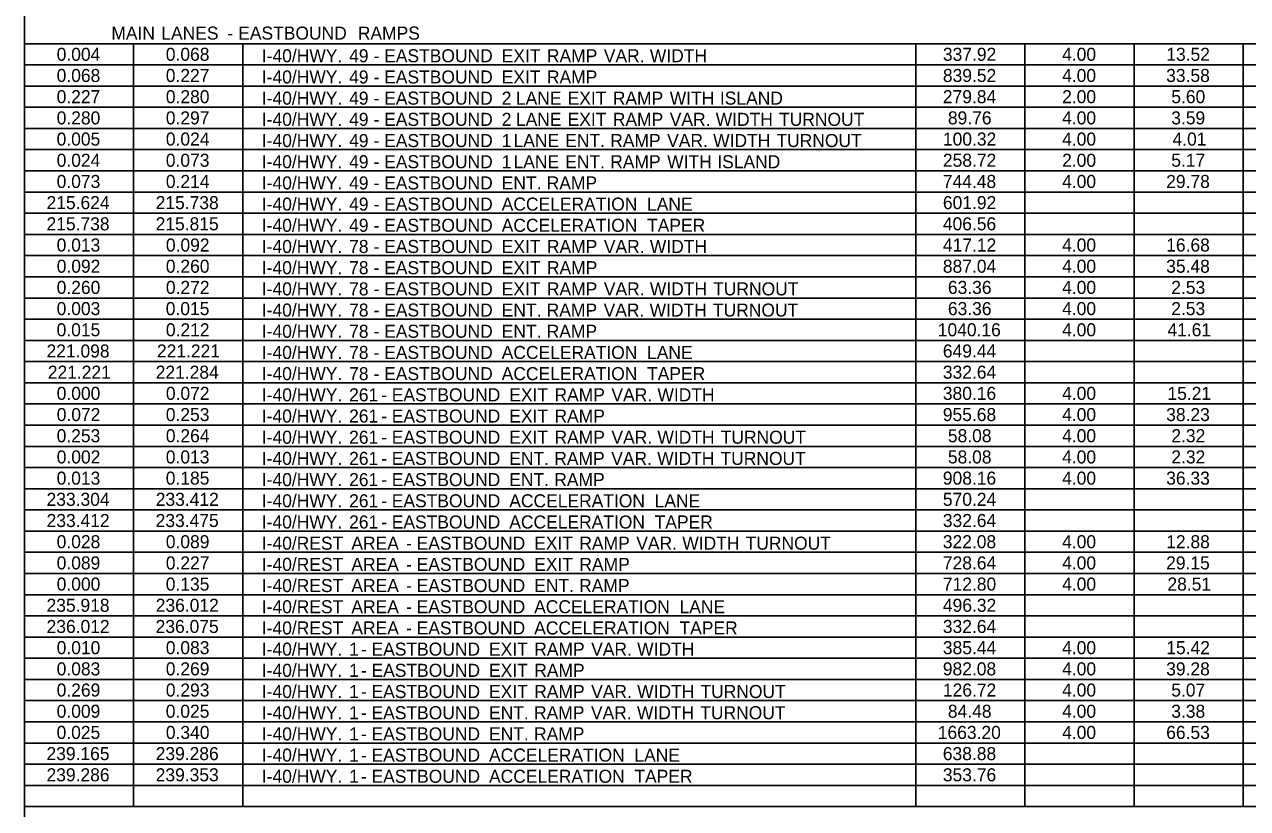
# Model space of a CAD drawing. Extents: x 2261867 to 2275370, y -3124789 to -3122260.
# Drawn here: x 2269380 to 2269943, y -3123269 to -3122908 of the extents above; entities that cross this region are included whole.
import ezdxf

# ---------------------------------------------------------------- set-up
doc = ezdxf.new("R2010")
doc.units = 0
doc.layers.add('Default', color=7, linetype='Continuous')

msp = doc.modelspace()

# ---------------------------------------------------------------- linework, layer by layer
at = {"layer": 'Default'}
for p, q in [((2269380.47, -3123434.1), (2269380.47, -3122273.85)), ((2269380.47, -3123434.1), (2269380.47, -3122273.85)), ((2269380.47, -3122917.35), (2270507.08, -3122917.35)), ((2269430.68, -3123268.35), (2269430.68, -3122917.35)), ((2269480.89, -3123268.35), (2269480.89, -3122917.35)), ((2269480.89, -3123268.35), (2269480.89, -3122917.35)), ((2269790.46, -3123268.35), (2269790.46, -3122917.35)), ((2269790.46, -3123268.35), (2269790.46, -3122917.35)), ((2269840.67, -3123268.35), (2269840.67, -3122917.35)), ((2269840.67, -3123268.35), (2269840.67, -3122917.35)), ((2269890.88, -3123268.35), (2269890.88, -3122917.35)), ((2269890.88, -3123268.35), (2269890.88, -3122917.35)), ((2269941.09, -3123268.35), (2269941.09, -3122917.35)), ((2269941.09, -3123268.35), (2269941.09, -3122917.35)), ((2269380.47, -3122927.1), (2270507.08, -3122927.1)), ((2269430.68, -3123268.35), (2269430.68, -3122927.1)), ((2269380.47, -3122936.85), (2270507.08, -3122936.85)), ((2269380.47, -3122946.6), (2270507.08, -3122946.6)), ((2269380.47, -3122956.35), (2270507.08, -3122956.35)), ((2269380.47, -3122966.1), (2270507.08, -3122966.1)), ((2269380.47, -3122975.85), (2270507.08, -3122975.85)), ((2269380.47, -3122985.6), (2270507.08, -3122985.6)), ((2269380.47, -3122995.35), (2270507.08, -3122995.35)), ((2269380.47, -3123005.1), (2270507.08, -3123005.1)), ((2269380.47, -3123014.85), (2270507.08, -3123014.85)), ((2269380.47, -3123024.6), (2270507.08, -3123024.6)), ((2269380.47, -3123034.35), (2270507.08, -3123034.35)), ((2269380.47, -3123044.1), (2270507.08, -3123044.1)), ((2269380.47, -3123053.85), (2270507.08, -3123053.85)), ((2269380.47, -3123063.6), (2270507.08, -3123063.6)), ((2269380.47, -3123073.35), (2270507.08, -3123073.35)), ((2269380.47, -3123083.1), (2270507.08, -3123083.1)), ((2269380.47, -3123092.85), (2270507.08, -3123092.85)), ((2269380.47, -3123102.6), (2270507.08, -3123102.6)), ((2269380.47, -3123112.35), (2270507.08, -3123112.35)), ((2269380.47, -3123122.1), (2270507.08, -3123122.1)), ((2269380.47, -3123131.85), (2270507.08, -3123131.85)), ((2269380.47, -3123141.6), (2270507.08, -3123141.6)), ((2269380.47, -3123151.35), (2270507.08, -3123151.35)), ((2269380.47, -3123161.1), (2270507.08, -3123161.1)), ((2269380.47, -3123170.85), (2270507.08, -3123170.85)), ((2269380.47, -3123180.6), (2270507.08, -3123180.6)), ((2269380.47, -3123190.35), (2270507.08, -3123190.35)), ((2269380.47, -3123200.1), (2270507.08, -3123200.1)), ((2269380.47, -3123209.85), (2270507.08, -3123209.85)), ((2269380.47, -3123219.6), (2270507.08, -3123219.6)), ((2269380.47, -3123229.35), (2270507.08, -3123229.35)), ((2269380.47, -3123239.1), (2270507.08, -3123239.1)), ((2269380.47, -3123248.85), (2270507.08, -3123248.85)), ((2269380.47, -3123258.6), (2270507.08, -3123258.6)), ((2269380.47, -3123268.35), (2270507.08, -3123268.35)), ((2269380.47, -3123268.35), (2270507.08, -3123268.35))]:
    msp.add_line(p, q, dxfattribs=at)

# ---------------------------------------------------------------- texts
for s, p in [('MAIN', (2269420.44, -3122915.47)), (' LANES', (2269441.19, -3122915.47)), (' EASTBOUND', (2269476.58, -3122915.47)), (' RAMPS', (2269531.6, -3122915.47)), (' -', (2269471.53, -3122915.47)), ('0.004', (2269395.29, -3122925.22)), ('0.068', (2269445.49, -3122925.22)), ('I-40/HWY.', (2269489.67, -3122925.9)), (' 49', (2269527.59, -3122925.9)), (' EASTBOUND', (2269543.72, -3122925.9)), (' EXIT', (2269597.78, -3122925.9)), (' RAMP', (2269618.58, -3122925.9)), (' VAR.', (2269644.76, -3122925.9)), (' WIDTH', (2269665.93, -3122925.9)), ('337.92', (2269802.97, -3122925.22)), ('4.00', (2269857.82, -3122925.22)), ('13.52', (2269905.73, -3122925.22)), (' -', (2269538.87, -3122925.9)), ('0.068', (2269395.28, -3122934.97)), ('0.227', (2269445.49, -3122934.97)), ('I-40/HWY.', (2269489.67, -3122935.65)), (' 49', (2269527.59, -3122935.65)), (' EASTBOUND', (2269543.72, -3122935.65)), (' EXIT', (2269597.78, -3122935.65)), (' RAMP', (2269618.58, -3122935.65)), ('839.52', (2269802.97, -3122934.97)), ('4.00', (2269857.82, -3122934.97)), ('33.58', (2269905.69, -3122934.97)), (' -', (2269538.87, -3122935.65)), ('0.227', (2269395.28, -3122944.72)), ('0.280', (2269445.51, -3122944.72)), ('I-40/HWY.', (2269489.67, -3122945.4)), (' 49', (2269527.59, -3122945.4)), (' -', (2269538.87, -3122945.4)), (' EASTBOUND', (2269543.72, -3122945.4)), (' 2', (2269597.78, -3122945.4)), (' LANE', (2269604.33, -3122945.4)), (' EXIT', (2269628.11, -3122945.4)), (' RAMP', (2269648.9, -3122945.4)), (' WITH', (2269675.09, -3122945.4)), (' ISLAND', (2269698.16, -3122945.4)), ('279.84', (2269802.95, -3122944.72)), ('2.00', (2269857.82, -3122944.72)), ('5.60', (2269908.04, -3122944.72)), ('0.280', (2269395.29, -3122954.47)), ('0.297', (2269445.49, -3122954.47)), ('I-40/HWY.', (2269489.67, -3122955.15)), (' 49', (2269527.59, -3122955.15)), (' EASTBOUND', (2269543.72, -3122955.15)), (' 2', (2269597.78, -3122955.15)), (' TURNOUT', (2269725.37, -3122955.15)), ('89.76', (2269805.27, -3122954.47)), ('4.00', (2269857.82, -3122954.47)), ('3.59', (2269908.02, -3122954.47)), (' -', (2269538.87, -3122955.15)), (' LANE', (2269604.33, -3122955.15)), (' EXIT', (2269628.11, -3122955.15)), (' RAMP', (2269648.9, -3122955.15)), (' VAR.', (2269675.09, -3122955.15)), (' WIDTH', (2269696.25, -3122955.15)), ('0.005', (2269395.26, -3122964.22)), ('0.024', (2269445.51, -3122964.22)), ('I-40/HWY.', (2269489.67, -3122964.9)), (' 49', (2269527.59, -3122964.9)), (' EASTBOUND', (2269543.72, -3122964.9)), (' 1', (2269597.78, -3122964.9)), (' LANE', (2269603.23, -3122964.9)), (' ENT.', (2269627.01, -3122964.9)), (' RAMP', (2269647.7, -3122964.9)), (' VAR.', (2269673.89, -3122964.9)), (' WIDTH', (2269695.05, -3122964.9)), (' TURNOUT', (2269724.18, -3122964.9)), ('100.32', (2269802.97, -3122964.22)), ('4.00', (2269857.82, -3122964.22)), ('4.01', (2269908.6, -3122964.22)), (' -', (2269538.87, -3122964.9)), ('0.024', (2269395.29, -3122973.97)), ('0.073', (2269445.49, -3122973.97)), ('I-40/HWY.', (2269489.67, -3122974.65)), (' 49', (2269527.59, -3122974.65)), (' EASTBOUND', (2269543.72, -3122974.65)), (' 1', (2269597.78, -3122974.65)), (' LANE', (2269603.23, -3122974.65)), (' ENT.', (2269627.01, -3122974.65)), (' RAMP', (2269647.7, -3122974.65)), (' WITH', (2269673.89, -3122974.65)), (' ISLAND', (2269696.96, -3122974.65)), ('258.72', (2269802.97, -3122973.97)), ('2.00', (2269857.82, -3122973.97)), ('5.17', (2269908.02, -3122973.97)), (' -', (2269538.87, -3122974.65)), ('0.073', (2269395.28, -3122983.72)), ('0.214', (2269445.51, -3122983.72)), ('I-40/HWY.', (2269489.67, -3122984.4)), (' 49', (2269527.59, -3122984.4)), (' -', (2269538.87, -3122984.4)), (' EASTBOUND', (2269543.72, -3122984.4)), (' ENT.', (2269597.78, -3122984.4)), (' RAMP', (2269618.48, -3122984.4)), ('744.48', (2269802.93, -3122983.72)), ('4.00', (2269857.82, -3122983.72)), ('29.78', (2269905.69, -3122983.72)), ('215.624', (2269390.63, -3122993.47)), ('215.738', (2269440.83, -3122993.47)), ('I-40/HWY.', (2269489.67, -3122994.15)), (' 49', (2269527.59, -3122994.15)), (' EASTBOUND', (2269543.72, -3122994.15)), (' ACCELERATION', (2269597.78, -3122994.15)), (' LANE', (2269664.65, -3122994.15)), ('601.92', (2269802.97, -3122993.47)), (' -', (2269538.87, -3122994.15)), ('215.738', (2269390.62, -3123003.22)), ('215.815', (2269440.81, -3123003.22)), ('I-40/HWY.', (2269489.67, -3123003.9)), (' 49', (2269527.59, -3123003.9)), (' EASTBOUND', (2269543.72, -3123003.9)), (' ACCELERATION', (2269597.78, -3123003.9)), (' TAPER', (2269664.65, -3123003.9)), ('406.56', (2269802.94, -3123003.22)), (' -', (2269538.87, -3123003.9)), ('0.013', (2269395.28, -3123012.97)), ('0.092', (2269445.53, -3123012.97)), ('I-40/HWY.', (2269489.67, -3123013.65)), (' 78', (2269527.59, -3123013.65)), (' EASTBOUND', (2269543.72, -3123013.65)), (' EXIT', (2269597.78, -3123013.65)), (' RAMP', (2269618.58, -3123013.65)), (' VAR.', (2269644.76, -3123013.65)), (' WIDTH', (2269665.93, -3123013.65)), ('417.12', (2269802.97, -3123012.97)), ('4.00', (2269857.82, -3123012.97)), ('16.68', (2269905.69, -3123012.97)), (' -', (2269538.87, -3123013.65)), ('0.092', (2269395.31, -3123022.72)), ('0.260', (2269445.51, -3123022.72)), ('I-40/HWY.', (2269489.67, -3123023.4)), (' 78', (2269527.59, -3123023.4)), (' -', (2269538.87, -3123023.4)), (' EASTBOUND', (2269543.72, -3123023.4)), (' EXIT', (2269597.78, -3123023.4)), (' RAMP', (2269618.58, -3123023.4)), ('887.04', (2269802.95, -3123022.72)), ('4.00', (2269857.82, -3123022.72)), ('35.48', (2269905.69, -3123022.72)), ('0.260', (2269395.29, -3123032.47)), ('0.272', (2269445.53, -3123032.47)), ('I-40/HWY.', (2269489.67, -3123033.15)), (' 78', (2269527.59, -3123033.15)), (' EASTBOUND', (2269543.72, -3123033.15)), (' EXIT', (2269597.78, -3123033.15)), (' RAMP', (2269618.58, -3123033.15)), (' VAR.', (2269644.76, -3123033.15)), (' WIDTH', (2269665.93, -3123033.15)), (' TURNOUT', (2269695.05, -3123033.15)), ('63.36', (2269805.27, -3123032.47)), ('4.00', (2269857.82, -3123032.47)), ('2.53', (2269908.02, -3123032.47)), (' -', (2269538.87, -3123033.15)), ('0.003', (2269395.28, -3123042.22)), ('0.015', (2269445.47, -3123042.22)), ('I-40/HWY.', (2269489.67, -3123042.9)), (' 78', (2269527.59, -3123042.9)), (' EASTBOUND', (2269543.72, -3123042.9)), (' ENT.', (2269597.78, -3123042.9)), (' RAMP', (2269618.48, -3123042.9)), (' VAR.', (2269644.66, -3123042.9)), (' WIDTH', (2269665.83, -3123042.9)), (' TURNOUT', (2269694.95, -3123042.9)), ('63.36', (2269805.27, -3123042.22)), ('4.00', (2269857.82, -3123042.22)), ('2.53', (2269908.02, -3123042.22)), (' -', (2269538.87, -3123042.9)), ('0.015', (2269395.26, -3123051.97)), ('0.212', (2269445.53, -3123051.97)), ('I-40/HWY.', (2269489.67, -3123052.65)), (' 78', (2269527.59, -3123052.65)), (' -', (2269538.87, -3123052.65)), (' EASTBOUND', (2269543.72, -3123052.65)), (' ENT.', (2269597.78, -3123052.65)), (' RAMP', (2269618.48, -3123052.65)), ('1040.16', (2269800.61, -3123051.97)), ('4.00', (2269857.82, -3123051.97)), ('41.61', (2269906.27, -3123051.97)), ('221.098', (2269390.62, -3123061.72)), ('221.221', (2269441.41, -3123061.72)), ('649.44', (2269802.95, -3123061.72)), ('I-40/HWY.', (2269489.67, -3123062.4)), (' 78', (2269527.59, -3123062.4)), (' -', (2269538.87, -3123062.4)), (' EASTBOUND', (2269543.72, -3123062.4)), (' ACCELERATION', (2269597.78, -3123062.4)), (' LANE', (2269664.65, -3123062.4)), ('221.221', (2269391.2, -3123071.47)), ('221.284', (2269440.85, -3123071.47)), ('I-40/HWY.', (2269489.67, -3123072.15)), (' 78', (2269527.59, -3123072.15)), (' EASTBOUND', (2269543.72, -3123072.15)), (' ACCELERATION', (2269597.78, -3123072.15)), (' TAPER', (2269664.65, -3123072.15)), ('332.64', (2269802.95, -3123071.47)), (' -', (2269538.87, -3123072.15)), ('0.000', (2269395.29, -3123081.22)), ('0.072', (2269445.53, -3123081.22)), ('I-40/HWY.', (2269489.67, -3123081.9)), (' 261', (2269527.59, -3123081.9)), (' EASTBOUND', (2269547.21, -3123081.9)), (' EXIT', (2269601.27, -3123081.9)), (' RAMP', (2269622.07, -3123081.9)), (' VAR.', (2269648.25, -3123081.9)), (' WIDTH', (2269669.42, -3123081.9)), ('380.16', (2269802.94, -3123081.22)), ('4.00', (2269857.82, -3123081.22)), ('15.21', (2269906.27, -3123081.22)), (' -', (2269542.36, -3123081.9)), ('0.072', (2269395.31, -3123090.97)), ('0.253', (2269445.49, -3123090.97)), ('I-40/HWY.', (2269489.67, -3123091.65)), (' 261', (2269527.59, -3123091.65)), (' -', (2269542.36, -3123091.65)), (' EASTBOUND', (2269547.21, -3123091.65)), (' EXIT', (2269601.27, -3123091.65)), (' RAMP', (2269622.07, -3123091.65)), ('955.68', (2269802.93, -3123090.97)), ('4.00', (2269857.82, -3123090.97)), ('38.23', (2269905.69, -3123090.97)), ('0.253', (2269395.28, -3123100.72)), ('0.264', (2269445.51, -3123100.72)), ('I-40/HWY.', (2269489.67, -3123101.4)), (' 261', (2269527.59, -3123101.4)), (' EASTBOUND', (2269547.21, -3123101.4)), (' TURNOUT', (2269698.54, -3123101.4)), ('58.08', (2269805.26, -3123100.72)), ('4.00', (2269857.82, -3123100.72)), ('2.32', (2269908.06, -3123100.72)), (' -', (2269542.36, -3123101.4)), (' EXIT', (2269601.27, -3123101.4)), (' RAMP', (2269622.07, -3123101.4)), (' VAR.', (2269648.25, -3123101.4)), (' WIDTH', (2269669.42, -3123101.4)), ('0.002', (2269395.31, -3123110.47)), ('0.013', (2269445.49, -3123110.47)), ('I-40/HWY.', (2269489.67, -3123111.15)), (' 261', (2269527.59, -3123111.15)), (' EASTBOUND', (2269547.21, -3123111.15)), (' ENT.', (2269601.27, -3123111.15)), (' RAMP', (2269621.97, -3123111.15)), (' VAR.', (2269648.15, -3123111.15)), (' WIDTH', (2269669.32, -3123111.15)), (' TURNOUT', (2269698.44, -3123111.15)), ('58.08', (2269805.26, -3123110.47)), ('4.00', (2269857.82, -3123110.47)), ('2.32', (2269908.06, -3123110.47)), (' -', (2269542.36, -3123111.15)), ('0.013', (2269395.28, -3123120.22)), ('0.185', (2269445.47, -3123120.22)), ('I-40/HWY.', (2269489.67, -3123120.9)), (' 261', (2269527.59, -3123120.9)), (' EASTBOUND', (2269547.21, -3123120.9)), (' ENT.', (2269601.27, -3123120.9)), (' RAMP', (2269621.97, -3123120.9)), ('908.16', (2269802.94, -3123120.22)), ('4.00', (2269857.82, -3123120.22)), ('36.33', (2269905.69, -3123120.22)), (' -', (2269542.36, -3123120.9)), ('233.304', (2269390.63, -3123129.97)), ('233.412', (2269440.87, -3123129.97)), ('I-40/HWY.', (2269489.67, -3123130.65)), (' 261', (2269527.59, -3123130.65)), (' -', (2269542.36, -3123130.65)), (' EASTBOUND', (2269547.21, -3123130.65)), (' ACCELERATION', (2269601.27, -3123130.65)), (' LANE', (2269668.14, -3123130.65)), ('570.24', (2269802.95, -3123129.97)), ('233.412', (2269390.65, -3123139.72)), ('233.475', (2269440.81, -3123139.72)), ('I-40/HWY.', (2269489.67, -3123140.4)), (' 261', (2269527.59, -3123140.4)), (' EASTBOUND', (2269547.21, -3123140.4)), (' ACCELERATION', (2269601.27, -3123140.4)), (' TAPER', (2269668.14, -3123140.4)), ('332.64', (2269802.95, -3123139.72)), (' -', (2269542.36, -3123140.4)), ('0.028', (2269395.28, -3123149.47)), ('0.089', (2269445.49, -3123149.47)), ('I-40/REST', (2269489.67, -3123150.15)), (' AREA', (2269528.63, -3123150.15)), (' EASTBOUND', (2269558.66, -3123150.15)), (' EXIT', (2269612.72, -3123150.15)), (' RAMP', (2269633.51, -3123150.15)), (' VAR.', (2269659.7, -3123150.15)), (' WIDTH', (2269680.86, -3123150.15)), (' TURNOUT', (2269709.99, -3123150.15)), ('322.08', (2269802.93, -3123149.47)), ('4.00', (2269857.82, -3123149.47)), ('12.88', (2269905.69, -3123149.47)), (' -', (2269553.8, -3123150.15)), ('0.089', (2269395.28, -3123159.22)), ('0.227', (2269445.49, -3123159.22)), ('I-40/REST', (2269489.67, -3123159.9)), (' AREA', (2269528.63, -3123159.9)), (' -', (2269553.8, -3123159.9)), (' EASTBOUND', (2269558.66, -3123159.9)), (' EXIT', (2269612.72, -3123159.9)), (' RAMP', (2269633.51, -3123159.9)), ('728.64', (2269802.95, -3123159.22)), ('4.00', (2269857.82, -3123159.22)), ('29.15', (2269905.67, -3123159.22)), ('0.000', (2269395.29, -3123168.97)), ('0.135', (2269445.47, -3123168.97)), ('I-40/REST', (2269489.67, -3123169.65)), (' AREA', (2269528.63, -3123169.65)), (' -', (2269553.8, -3123169.65)), (' EASTBOUND', (2269558.66, -3123169.65)), (' ENT.', (2269612.72, -3123169.65)), (' RAMP', (2269633.41, -3123169.65)), ('712.80', (2269802.95, -3123168.97)), ('4.00', (2269857.82, -3123168.97)), ('28.51', (2269906.27, -3123168.97)), ('235.918', (2269390.62, -3123178.72)), ('236.012', (2269440.87, -3123178.72)), ('I-40/REST', (2269489.67, -3123179.4)), (' AREA', (2269528.63, -3123179.4)), (' EASTBOUND', (2269558.66, -3123179.4)), (' ACCELERATION', (2269612.72, -3123179.4)), (' LANE', (2269679.58, -3123179.4)), ('496.32', (2269802.97, -3123178.72)), (' -', (2269553.8, -3123179.4)), ('236.012', (2269390.65, -3123188.47)), ('236.075', (2269440.81, -3123188.47)), ('I-40/REST', (2269489.67, -3123189.15)), (' AREA', (2269528.63, -3123189.15)), (' EASTBOUND', (2269558.66, -3123189.15)), (' ACCELERATION', (2269612.72, -3123189.15)), (' TAPER', (2269679.58, -3123189.15)), ('332.64', (2269802.95, -3123188.47)), (' -', (2269553.8, -3123189.15)), ('0.010', (2269395.29, -3123198.22)), ('0.083', (2269445.49, -3123198.22)), ('I-40/HWY.', (2269489.67, -3123198.9)), (' 1', (2269527.59, -3123198.9)), (' -', (2269533.04, -3123198.9)), (' EASTBOUND', (2269537.89, -3123198.9)), (' EXIT', (2269591.95, -3123198.9)), (' RAMP', (2269612.75, -3123198.9)), (' VAR.', (2269638.93, -3123198.9)), (' WIDTH', (2269660.1, -3123198.9)), ('385.44', (2269802.95, -3123198.22)), ('4.00', (2269857.82, -3123198.22)), ('15.42', (2269905.73, -3123198.22)), ('0.083', (2269395.28, -3123207.97)), ('0.269', (2269445.49, -3123207.97)), ('982.08', (2269802.93, -3123207.97)), ('4.00', (2269857.82, -3123207.97)), ('39.28', (2269905.69, -3123207.97)), ('I-40/HWY.', (2269489.67, -3123208.65)), (' 1', (2269527.59, -3123208.65)), (' -', (2269533.04, -3123208.65)), (' EASTBOUND', (2269537.89, -3123208.65)), (' EXIT', (2269591.95, -3123208.65)), (' RAMP', (2269612.75, -3123208.65)), ('0.269', (2269395.28, -3123217.72)), ('0.293', (2269445.49, -3123217.72)), ('I-40/HWY.', (2269489.67, -3123218.4)), (' 1', (2269527.59, -3123218.4)), (' EASTBOUND', (2269537.89, -3123218.4)), (' EXIT', (2269591.95, -3123218.4)), (' RAMP', (2269612.75, -3123218.4)), (' VAR.', (2269638.93, -3123218.4)), (' WIDTH', (2269660.1, -3123218.4)), (' TURNOUT', (2269689.22, -3123218.4)), ('126.72', (2269802.97, -3123217.72)), ('4.00', (2269857.82, -3123217.72)), ('5.07', (2269908.02, -3123217.72)), (' -', (2269533.04, -3123218.4)), ('0.009', (2269395.28, -3123227.47)), ('0.025', (2269445.47, -3123227.47)), ('I-40/HWY.', (2269489.67, -3123228.15)), (' 1', (2269527.59, -3123228.15)), (' EASTBOUND', (2269537.89, -3123228.15)), (' ENT.', (2269591.95, -3123228.15)), (' RAMP', (2269612.65, -3123228.15)), (' VAR.', (2269638.83, -3123228.15)), (' WIDTH', (2269660, -3123228.15)), (' TURNOUT', (2269689.12, -3123228.15)), ('84.48', (2269805.26, -3123227.47)), ('4.00', (2269857.82, -3123227.47)), ('3.38', (2269908.02, -3123227.47)), (' -', (2269533.04, -3123228.15)), ('0.025', (2269395.26, -3123237.22)), ('0.340', (2269445.51, -3123237.22)), ('I-40/HWY.', (2269489.67, -3123237.9)), (' 1', (2269527.59, -3123237.9)), (' -', (2269533.04, -3123237.9)), (' EASTBOUND', (2269537.89, -3123237.9)), (' ENT.', (2269591.95, -3123237.9)), (' RAMP', (2269612.65, -3123237.9)), ('1663.20', (2269800.62, -3123237.22)), ('4.00', (2269857.82, -3123237.22)), ('66.53', (2269905.69, -3123237.22)), ('239.165', (2269390.6, -3123246.97)), ('239.286', (2269440.83, -3123246.97)), ('I-40/HWY.', (2269489.67, -3123247.65)), (' 1', (2269527.59, -3123247.65)), (' EASTBOUND', (2269537.89, -3123247.65)), (' ACCELERATION', (2269591.95, -3123247.65)), (' LANE', (2269658.82, -3123247.65)), ('638.88', (2269802.93, -3123246.97)), (' -', (2269533.04, -3123247.65)), ('239.286', (2269390.62, -3123256.72)), ('239.353', (2269440.83, -3123256.72)), ('I-40/HWY.', (2269489.67, -3123257.4)), (' 1', (2269527.59, -3123257.4)), (' EASTBOUND', (2269537.89, -3123257.4)), (' ACCELERATION', (2269591.95, -3123257.4)), (' TAPER', (2269658.82, -3123257.4)), ('353.76', (2269802.94, -3123256.72)), (' -', (2269533.04, -3123257.4))]:
    msp.add_text(s, height=6, dxfattribs=at).set_placement(p)

doc.saveas('drawing.dxf')
